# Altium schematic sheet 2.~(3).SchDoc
size 420 x 297 mm
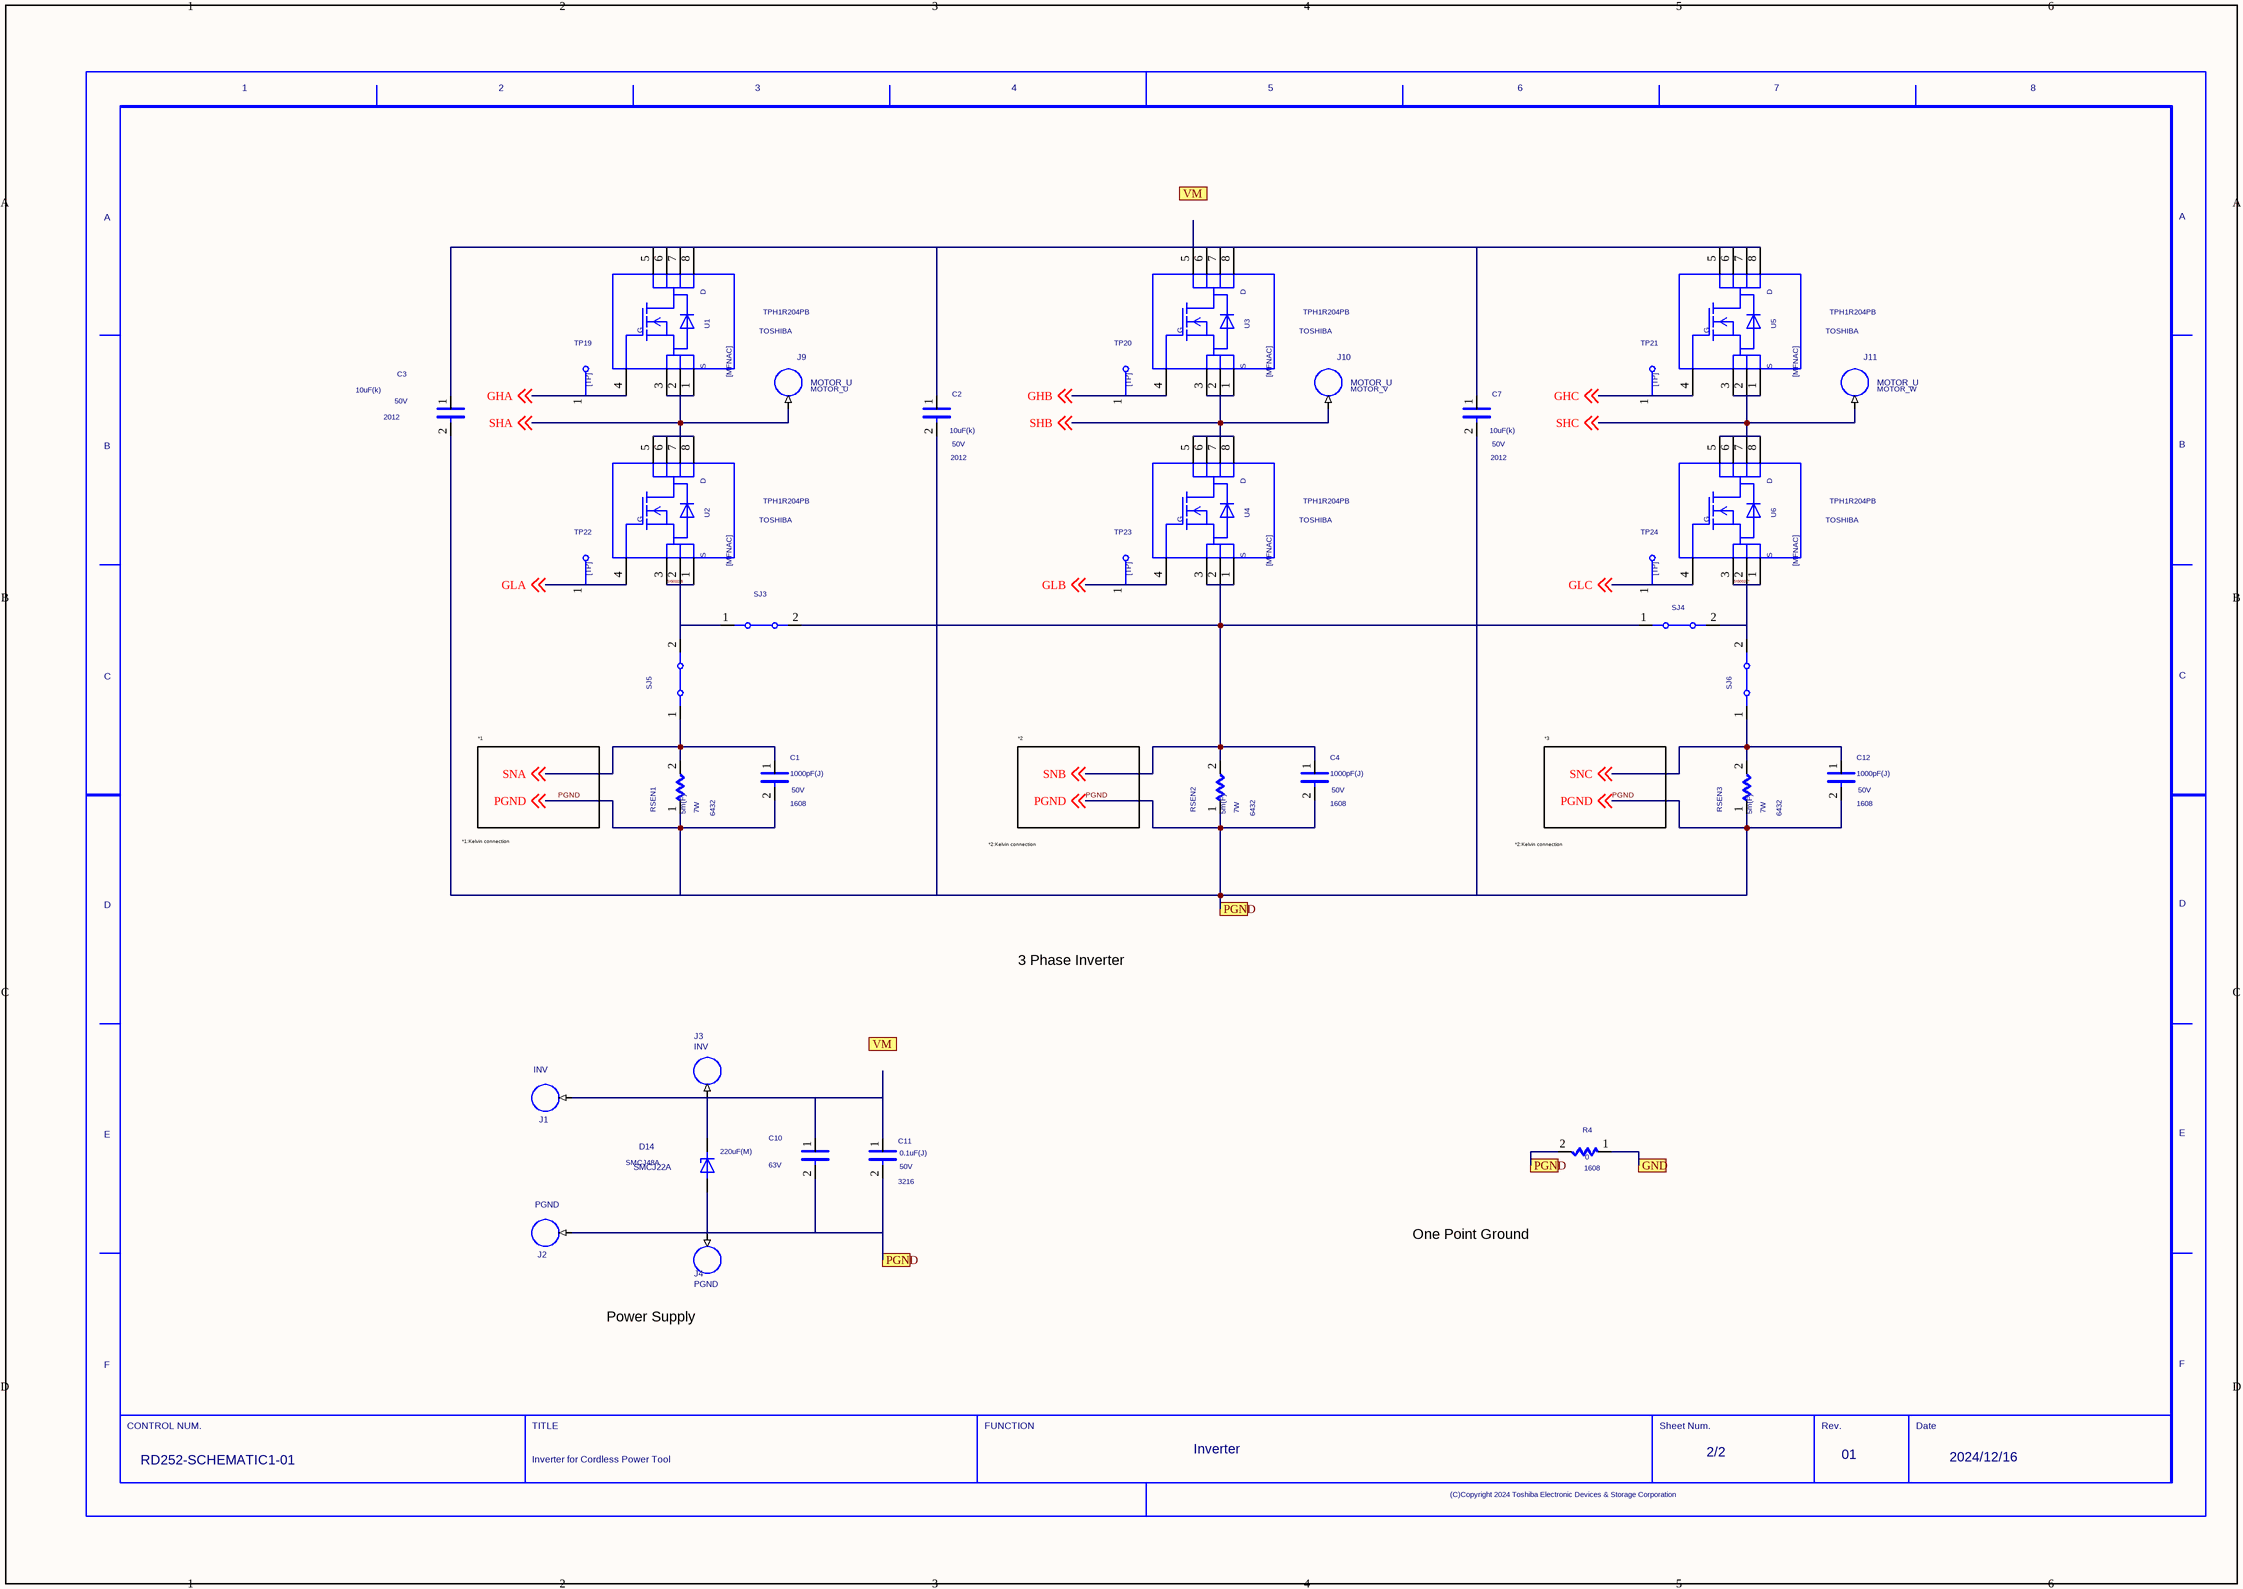
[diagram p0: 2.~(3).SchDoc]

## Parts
C1  SIZECODESMD: 1608  VAL2: 50V  VAL1: 1000pF(J)  (hidden comment: C)
C2  SIZECODESMD: 2012  VAL2: 50V  VAL1: 10uF(k)  (hidden comment: C)
C3  SIZECODESMD: 2012  VAL2: 50V  VAL1: 10uF(k)  (hidden comment: C)
C4  SIZECODESMD: 1608  VAL2: 50V  VAL1: 1000pF(J)  (hidden comment: C)
C7  SIZECODESMD: 2012  VAL2: 50V  VAL1: 10uF(k)  (hidden comment: C)
C10  VAL2: 63V  VAL1: 220uF(M)  (hidden comment: C)
C11  SIZECODESMD: 3216  VAL2: 50V  VAL1: 0.1uF(J)  (hidden comment: C)
C12  SIZECODESMD: 1608  VAL2: 50V  VAL1: 1000pF(J)  (hidden comment: C)
D14  SMCJ22A  VAL3: SMCJ48A  [DSMC]
J1  INV  [TP_SM]
J2  PGND  [TP_SM]
J3  INV  [TP_SM]
J4  PGND  [TP_SM]
J9  MOTOR_U  [TP_SM]
J10  MOTOR_U  VAL3: MOTOR_V  [TP_SM]
J11  MOTOR_U  VAL3: MOTOR_W  [TP_SM]
R4  SIZECODESMD: 1608  VAL1: 0  (hidden comment: R)
RSEN1  SIZECODESMD: 6432  VAL2: 7W  VAL1: 5m(F)  (hidden comment: R)
RSEN2  SIZECODESMD: 6432  VAL2: 7W  VAL1: 5m(F)  (hidden comment: R)
RSEN3  SIZECODESMD: 6432  VAL2: 7W  VAL1: 5m(F)  (hidden comment: R)
SJ3  JP  (value not drawn)
SJ4  JP  (value not drawn)
SJ5  JP  (value not drawn)
SJ6  JP  (value not drawn)
TP19  TP  (value not drawn)
TP20  TP  (value not drawn)
TP21  TP  (value not drawn)
TP22  TP  (value not drawn)
TP23  TP  (value not drawn)
TP24  TP  (value not drawn)
U1  USERCOMPTEXT3: TOSHIBA  VAL3: TPH1R204PB  (hidden comment: MFNAC)
U2  USERCOMPTEXT3: TOSHIBA  VAL3: TPH1R204PB  (hidden comment: MFNAC)
U3  USERCOMPTEXT3: TOSHIBA  VAL3: TPH1R204PB  (hidden comment: MFNAC)
U4  USERCOMPTEXT3: TOSHIBA  VAL3: TPH1R204PB  (hidden comment: MFNAC)
U5  USERCOMPTEXT3: TOSHIBA  VAL3: TPH1R204PB  (hidden comment: MFNAC)
U6  USERCOMPTEXT3: TOSHIBA  VAL3: TPH1R204PB  (hidden comment: MFNAC)
U?  DATE: 2024/12/16  FUNCTION: Inverter  TITLE: Inverter for Cordless Power Tool  REVISION: 01  SHEETNUMBER: 2/2  DRAWINGNUMBER: RD252-SCHEMATIC1-01  (hidden comment: WAKU_DEF100)

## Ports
GND, PGND, VM

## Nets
GHA: TP19.1 U1.4 ; off-sheet GHA
GHB: TP20.1 U3.4 ; off-sheet GHB
GHC: TP21.1 U5.4 ; off-sheet GHC
GLA: TP22.1 U2.4 ; off-sheet GLA
GLB: TP23.1 U4.4 ; off-sheet GLB
GLC: TP24.1 U6.4 ; off-sheet GLC
GND: R4.1 ; port GND
PGND: C1.2 C2.2 C3.2 C4.2 C7.2 C10.2 C11.2 C12.2 D14.A J2.1 J4.1 R4.2 RSEN1.1 RSEN2.1 RSEN3.1 ; off-sheet PGND, port PGND
SHA: J9.1 U1.1 U1.2 U1.3 U2.5 U2.6 U2.7 U2.8 ; off-sheet SHA
SHB: J10.1 U3.1 U3.2 U3.3 U4.5 U4.6 U4.7 U4.8 ; off-sheet SHB
SHC: J11.1 U5.1 U5.2 U5.3 U6.5 U6.6 U6.7 U6.8 ; off-sheet SHC
SIG00255: SJ3.1 SJ5.2 U2.1 U2.2 U2.3
SIG00257: SJ4.2 SJ6.2 U6.1 U6.2 U6.3
SNA: C1.1 RSEN1.2 SJ5.1 ; off-sheet SNA
SNB: C4.1 RSEN2.2 SJ3.2 SJ4.1 U4.1 U4.2 U4.3 ; off-sheet SNB
SNC: C12.1 RSEN3.2 SJ6.1 ; off-sheet SNC
NetC2_1: C2.1 C3.1 C7.1 U1.5 U1.6 U1.7 U1.8 U3.5 U3.6 U3.7 U3.8 U5.5 U5.6 U5.7 U5.8
NetC10_1: C10.1 C11.1 D14.C J1.1 J3.1

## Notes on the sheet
- *1
- *2
- *3
- *1:Kelvin connection
  from RSEN1 and C1 to U8
- *2:Kelvin connection
  from RSEN2 and C4 to U8
- *2:Kelvin connection
  from RSEN3 and C12 to U8
- 3 Phase Inverter
- One Point Ground
- Power Supply

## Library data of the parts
C1-C4 C7 C10-C12 = C: TIME: 17:22:43; UPDATEUSER: t5459927; SAVECOUNT: 1; ORIGINALSYMBOLORIGIN: (-2540,5080)
D14 = SMCJ22A_D14: TIME: 10:49:12; UPDATEUSER: sptcae09; UPDATETIME: 10:49:13; SAVECOUNT: 2; ORIGIN: Altium; MF: Littelfuse; GATENAME_1: G$1; OriginalSymbolOrigin: (0,1270); INSTANCENAME: INS1233
J1 = 1X1HEADER_J1: TIME: 10:49:17; UPDATEUSER: sptcae09; UPDATETIME: 10:49:18; SAVECOUNT: 3; GATENAME_1: G$1; ORIGIN: Altium; OriginalSymbolOrigin: (-5080,2540); VAL3: Through Hole; INSTANCENAME: INS1187
J2 = 1X1HEADER_J2: TIME: 10:49:18; UPDATEUSER: sptcae09; UPDATETIME: 10:49:19; SAVECOUNT: 3; GATENAME_1: G$1; ORIGIN: Altium; OriginalSymbolOrigin: (-5080,2540); VAL3: Through Hole; INSTANCENAME: INS1195
J3 = 1X1HEADER_J3: TIME: 10:49:12; UPDATEUSER: sptcae09; SAVECOUNT: 3; GATENAME_1: G$1; ORIGIN: Altium; OriginalSymbolOrigin: (-2540,5080); VAL3: Through Hole; INSTANCENAME: INS1429
J4 = 1X1HEADER_J4: TIME: 10:49:13; UPDATEUSER: sptcae09; SAVECOUNT: 3; GATENAME_1: G$1; ORIGIN: Altium; OriginalSymbolOrigin: (-2540,0); VAL3: Through Hole; INSTANCENAME: INS1437
J9-J11 = 1X1HEADER_J9: TIME: 10:49:11; UPDATEUSER: sptcae09; UPDATETIME: 10:49:12; SAVECOUNT: 3; GATENAME_1: G$1; ORIGIN: Altium; OriginalSymbolOrigin: (-2540,5080); USEWITHLAYOUT: YES; INSTANCENAME: INS1015
R4 = R: TIME: 17:22:43; UPDATEUSER: t5459927; SAVECOUNT: 1; ORIGINALSYMBOLORIGIN: (2540,2540); VAL2: 1A
RSEN1-RSEN3 = R: TIME: 17:22:43; UPDATEUSER: t5459927; SAVECOUNT: 1; ORIGINALSYMBOLORIGIN: (2540,2540)
SJ3-SJ6 = JP: OriginalSymbolOrigin: (2540,5080); VAL3: Solder_Jumper; COMP: SJ; SAVECOUNT: 0
TP19-TP24 = TP: TIME: 16:12:21; UPDATEUSER: fukuda-y; UPDATETIME: 16:18:11; SAVECOUNT: 2; SAVEAREA0: -242,-92,12810,7836; OriginalSymbolOrigin: (0,7620)
U1-U6 = MFNAC: TIME: 18:29:30; UPDATEUSER: 19990028; UPDATETIME: 14:45:16; SAVECOUNT: 26; SAVEAREA0: -10143,-336,37609,28718; OriginalSymbolOrigin: (5080,25400)
U? = WAKU_DEF100_1: TIME: 14:30:25; UPDATEUSER: sptcae09; UPDATETIME: 10:34:52; SAVECOUNT: 3; PLOTTIME: HH:MM; SAVEAREA0: -63393,-16950,474261,314592; ORIGINALSYMBOLORIGIN: (0,0); SHTSAVECOUNT: 40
